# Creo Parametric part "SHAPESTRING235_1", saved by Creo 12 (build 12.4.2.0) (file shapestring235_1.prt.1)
Units: Custom; MM, KILOGRAM, SECS

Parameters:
  PTC_WM_ITERATION = "0"
  PTC_WM_VERSION = "-.0"
  PTC_WM_LIFECYCLE_STATE = "In Work"
  PTC_WM_LIFECYCLE = "MO_CADDocument"
  PTC_WM_CREATED_BY = "Maximilian Roepper (Z0017RMS: MO)"
  PTC_WM_CREATED_ON = "18-Sep-26 11:36:42 AM"
  PTC_WM_MODIFIED_BY = "Maximilian Roepper (Z0017RMS: MO)"
  PTC_WM_MODIFIED_ON = "18-Sep-26 11:36:46 AM"
  PDMLINKNUMBER = "PDM000071455120"
  PTC_WM_NAME = "shapestring235_1.prt"
  PTC_WM_NUMBER = "PDM000071455120"

Other parameters: WEIGHT, WEIGHT_FACTOR, WEIGHT_ADD, _MASS_TEMP, _DIFF_TEMP, MC_ERRORS, SUPPLIER

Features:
  1. coordinate system
  2. datum plane "PRT_YZ"
  3. datum plane "PRT_XY"
  4. datum plane "PRT_XZ"
  5. coordinate system
  6. datum axis
  7. datum axis
  8. datum axis
  9. coordinate system
  10. imported feature
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
Other named items: PRT, SIEMENS_MO, DRW_VIEW_ORG, PRT_X, PRT_Y, PRT_Z, CS0, ROUGH_GROB

Layers: 00_STD_CSYS-KSYS, 01_STD_PLANES-EBENEN, 02_STD_AXES-ACHSEN, 03_STD_CSYS-KSYS, 24_IMPORT_FEAT-IMPORT_KE, INTFCLR

Surfaces: 1 plane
